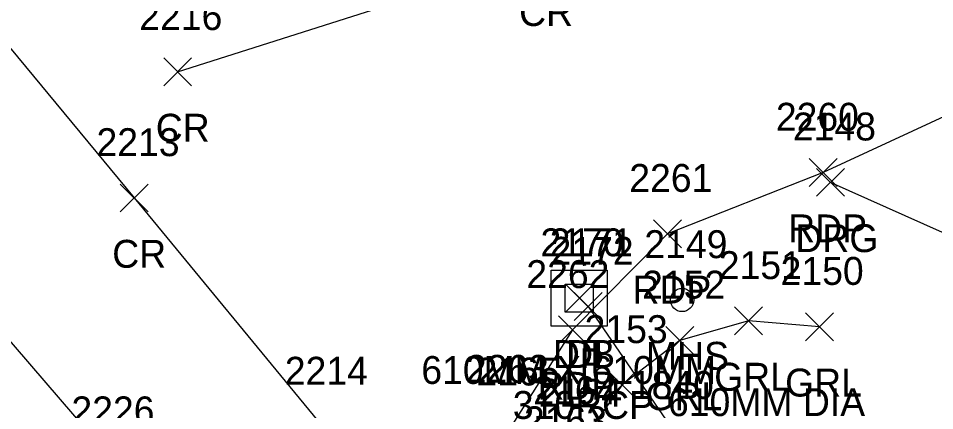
# Model space of a CAD drawing. Extents: x 1616726 to 1619875, y 273782 to 276557.
# Drawn here: x 1616930.2 to 1616995.8, y 276345.2 to 276373.3 of the extents above; entities that cross this region are included whole.
import ezdxf

# ---------------------------------------------------------------- set-up
doc = ezdxf.new("R2010")
doc.units = 0
for name, color, linetype in [('D_A', 7, 'Continuous'), ('D_C', 7, 'Continuous'), ('D_I', 7, 'Continuous'), ('D_TIC', 7, 'Continuous'), ('DCP', 7, 'Continuous'), ('DS', 7, 'Continuous'), ('P_A', 7, 'Continuous'), ('P_I', 7, 'Continuous'), ('P_TIC', 7, 'Continuous'), ('PET', 7, 'Continuous'), ('PRC', 7, 'Continuous'), ('R_A', 7, 'Continuous'), ('R_I', 7, 'Continuous'), ('R_TIC', 7, 'Continuous'), ('RDG', 7, 'Continuous'), ('RGR', 7, 'Continuous'), ('S_I', 7, 'Continuous'), ('U_A', 7, 'Continuous'), ('U_C', 7, 'Continuous'), ('U_I', 7, 'Continuous'), ('USMH', 7, 'Continuous')]:
    doc.layers.add(name, color=color, linetype=linetype)

msp = doc.modelspace()

# ---------------------------------------------------------------- linework, layer by layer
at = {"layer": 'D_TIC'}
for points in [[(1616969.363, 276352.225), (1616971.363, 276354.225)], [(1616971.363, 276352.225), (1616969.363, 276354.225)], [(1616969.991, 276351.622), (1616971.991, 276353.622)], [(1616971.991, 276351.622), (1616969.991, 276353.622)]]:
    msp.add_lwpolyline(points, dxfattribs=at)
at = {"layer": 'DCP'}
msp.add_lwpolyline([(1616970.991, 276352.622), (1616994.184, 276318.837)], dxfattribs=at)
at = {"layer": 'DS'}
for p, q in [((1616968.35, 276355.225), (1616972.35, 276355.225)), ((1616968.35, 276351.225), (1616968.35, 276355.225)), ((1616972.35, 276355.225), (1616972.35, 276351.225)), ((1616969.35, 276352.225), (1616969.35, 276354.225)), ((1616969.35, 276354.225), (1616971.35, 276354.225)), ((1616971.35, 276354.225), (1616971.35, 276352.225)), ((1616970.355, 276353.227), (1616970.355, 276353.227)), ((1616970.355, 276353.227), (1616970.355, 276353.227)), ((1616971.35, 276352.225), (1616969.35, 276352.225)), ((1616972.35, 276351.225), (1616968.35, 276351.225))]:
    msp.add_line(p, q, dxfattribs=at)
at = {"layer": 'P_TIC'}
for points in [[(1616940.588, 276368.44), (1616942.588, 276370.44)], [(1616942.588, 276368.44), (1616940.588, 276370.44)], [(1616986.83, 276361.226), (1616988.83, 276363.226)], [(1616988.83, 276361.226), (1616986.83, 276363.226)], [(1616937.47, 276359.406), (1616939.47, 276361.406)], [(1616939.47, 276359.406), (1616937.47, 276361.406)], [(1616975.678, 276356.843), (1616977.678, 276358.843)], [(1616977.678, 276356.843), (1616975.678, 276358.843)], [(1616968.871, 276349.951), (1616970.871, 276351.951)], [(1616970.871, 276349.951), (1616968.871, 276351.951)]]:
    msp.add_lwpolyline(points, dxfattribs=at)
at = {"layer": 'PET'}
msp.add_lwpolyline([(1617014.404, 276374.536), (1616987.83, 276362.226), (1616976.678, 276357.843), (1616969.871, 276350.951), (1616965.537, 276344.162), (1616964.241, 276339.945), (1616963.659, 276334.926), (1616964.456, 276330.122), (1616966.241, 276325.428), (1616953.454, 276321.458), (1616940.91, 276317.633), (1616926.659, 276333.645), (1616912.071, 276350.842), (1616900.384, 276364.101), (1616887.78, 276376.027)], dxfattribs=at)
at = {"layer": 'PRC'}
for points in [[(1616953.087, 276321.774), (1616937.295, 276341.184), (1616917.352, 276364.385), (1616896.093, 276388.679), (1616870.6, 276416.951), (1616844.423, 276444.9), (1616816.583, 276473.522), (1616795.842, 276493.985), (1616777.166, 276512.186)], [(1616941.588, 276369.44), (1616967.613, 276377.73), (1616992.446, 276385.734), (1617015.177, 276393.532), (1617039.999, 276403.877), (1617060.605, 276414.358), (1617077.777, 276424.695), (1617090.544, 276433.249), (1617097.772, 276438.739)], [(1616895.968, 276413.196), (1616909.569, 276395.506), (1616925.638, 276375.937), (1616938.47, 276360.406), (1616951.957, 276344.025), (1616962.869, 276330.949)]]:
    msp.add_lwpolyline(points, dxfattribs=at)
at = {"layer": 'R_TIC'}
for points in [[(1616987.347, 276360.528), (1616989.347, 276362.528)], [(1616989.347, 276360.528), (1616987.347, 276362.528)], [(1616981.476, 276350.595), (1616983.476, 276352.595)], [(1616983.476, 276350.595), (1616981.476, 276352.595)], [(1616986.556, 276350.179), (1616988.556, 276352.179)], [(1616988.556, 276350.179), (1616986.556, 276352.179)], [(1616976.549, 276349.197), (1616978.549, 276351.197)], [(1616978.549, 276349.197), (1616976.549, 276351.197)], [(1616972.431, 276346.007), (1616974.431, 276348.007)], [(1616974.431, 276346.007), (1616972.431, 276348.007)]]:
    msp.add_lwpolyline(points, dxfattribs=at)
at = {"layer": 'RDG'}
msp.add_lwpolyline([(1617041.289, 276342.767), (1617023.284, 276345.113), (1617005.954, 276353.65), (1616988.347, 276361.528)], dxfattribs=at)
at = {"layer": 'RGR'}
msp.add_lwpolyline([(1616987.556, 276351.179), (1616982.476, 276351.595), (1616977.549, 276350.197), (1616973.431, 276347.007), (1616970.155, 276342.461), (1616968.626, 276337.48), (1616968.502, 276333.447), (1616969.439, 276329.892), (1616970.958, 276327.471)], dxfattribs=at)
at = {"layer": 'USMH'}
for p, q in [((1616977.717, 276353.096), (1616977.717, 276353.096)), ((1616978.55, 276353.096), (1616978.55, 276353.096))]:
    msp.add_line(p, q, dxfattribs=at)
msp.add_circle((1616977.717, 276353.096), 0.833, dxfattribs=at)

# ---------------------------------------------------------------- texts
at = {"layer": 'D_A'}
for s, p in [('DIB', (1616968.466, 276348.225)), ('DI', (1616969.41, 276348.227)), ('P', (1616970.369, 276347.622))]:
    msp.add_text(s, height=2, dxfattribs=at).set_placement(p)
at = {"layer": 'D_C'}
for s, p in [('610MM X 610MM', (1616959.042, 276347.081)), ('310RCP', (1616965.595, 276344.574))]:
    msp.add_text(s, height=2, dxfattribs=at).set_placement(p)
at = {"layer": 'D_I'}
for s, p in [('2170', (1616967.575, 276356.227)), ('2171', (1616968.237, 276356.225)), ('2172', (1616968.298, 276355.622))]:
    msp.add_text(s, height=2, dxfattribs=at).set_placement(p)
at = {"layer": 'P_A'}
for s, p in [('CR', (1616966.046, 276372.73)), ('CR', (1616940.022, 276364.44)), ('RDP', (1616985.318, 276357.226)), ('CR', (1616936.903, 276355.406)), ('RDP', (1616974.166, 276352.843)), ('RDP', (1616967.359, 276345.951))]:
    msp.add_text(s, height=2, dxfattribs=at).set_placement(p)
at = {"layer": 'P_I'}
for s, p in [('2216', (1616938.84, 276372.44)), ('2260', (1616984.436, 276365.226)), ('2213', (1616935.777, 276363.406)), ('2261', (1616973.937, 276360.843)), ('2262', (1616966.564, 276353.951)), ('2214', (1616949.264, 276347.025)), ('2263', (1616962.23, 276347.162)), ('2226', (1616933.98, 276344.184))]:
    msp.add_text(s, height=2, dxfattribs=at).set_placement(p)
at = {"layer": 'R_A'}
for s, p in [('DRG', (1616985.835, 276356.528)), ('GRL', (1616980.019, 276346.595)), ('GRL', (1616985.099, 276346.179)), ('GRL', (1616975.092, 276345.197))]:
    msp.add_text(s, height=2, dxfattribs=at).set_placement(p)
at = {"layer": 'R_I'}
for s, p in [('2148', (1616985.654, 276364.528)), ('2151', (1616980.35, 276354.595)), ('2150', (1616984.776, 276354.179)), ('2152', (1616974.856, 276353.197)), ('2153', (1616970.739, 276350.007)), ('2165', (1616962.994, 276346.971)), ('2164', (1616967.061, 276345.629)), ('2154', (1616967.462, 276345.461)), ('2163', (1616966.392, 276343.474))]:
    msp.add_text(s, height=2, dxfattribs=at).set_placement(p)
at = {"layer": 'S_I'}
msp.add_text('1840', height=2, dxfattribs=at).set_placement((1616974.048, 276346.005))
at = {"layer": 'U_A'}
msp.add_text('MHS', height=2, dxfattribs=at).set_placement((1616975.134, 276348.096))
at = {"layer": 'U_C'}
msp.add_text('610MM DIA', height=2, dxfattribs=at).set_placement((1616976.712, 276344.776))
at = {"layer": 'U_I'}
msp.add_text('2149', height=2, dxfattribs=at).set_placement((1616975.016, 276356.096))

doc.saveas('drawing.dxf')
